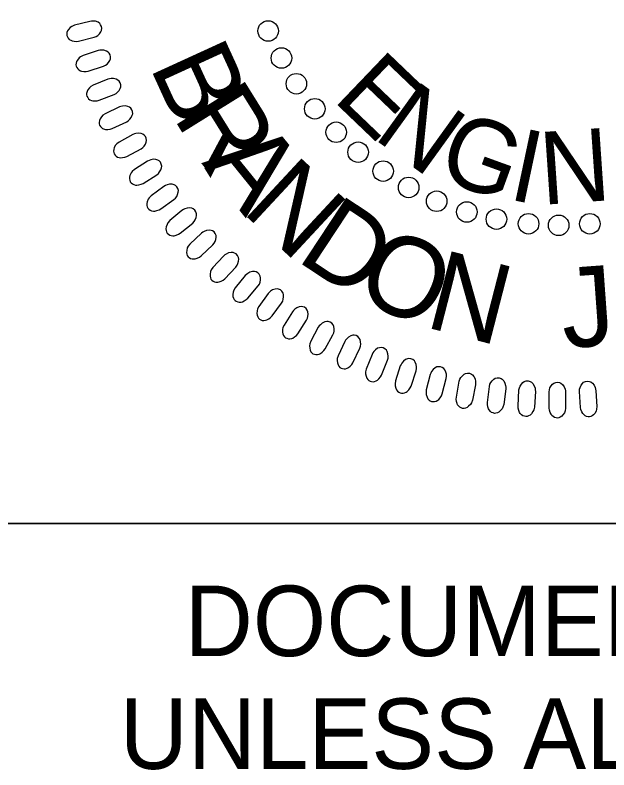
# Model space of a CAD drawing. Extents: x 502400 to 509344, y 448070 to 484209.
# Drawn here: x 507076.9 to 507123.2, y 484026.9 to 484085.8 of the extents above; entities that cross this region are included whole.
import ezdxf

# ---------------------------------------------------------------- set-up
doc = ezdxf.new("R2010")
doc.units = 0
for name, color, linetype in [('Sheet PE Seal Cell', 7, 'Continuous'), ('Sheet Profile CELL', 7, 'Continuous'), ('Sheet Sticker Exception Certification CELL', 7, 'Continuous')]:
    doc.layers.add(name, color=color, linetype=linetype)

msp = doc.modelspace()

# ---------------------------------------------------------------- linework, layer by layer
at = {"layer": 'Sheet PE Seal Cell'}
for points in [[(507082.689, 484085.332), (507081.501, 484085.028), (507081.298, 484084.937), (507081.175, 484084.852), (507081.039, 484084.701), (507080.957, 484084.58), (507080.907, 484084.451), (507080.895, 484084.34), (507080.903, 484084.226), (507080.95, 484084.123), (507081.009, 484084.015), (507081.093, 484083.928), (507081.216, 484083.851), (507081.308, 484083.813), (507081.469, 484083.785), (507081.658, 484083.772), (507081.818, 484083.79), (507083.037, 484084.094), (507083.196, 484084.158), (507083.32, 484084.237), (507083.452, 484084.363), (507083.56, 484084.506), (507083.613, 484084.62), (507083.632, 484084.787), (507083.614, 484084.937), (507083.538, 484085.072), (507083.464, 484085.161), (507083.336, 484085.26), (507083.142, 484085.333), (507082.951, 484085.354), (507082.818, 484085.35)], [(507083.343, 484083.049), (507082.176, 484082.67), (507081.979, 484082.567), (507081.862, 484082.475), (507081.735, 484082.315), (507081.661, 484082.188), (507081.62, 484082.057), (507081.615, 484081.946), (507081.63, 484081.833), (507081.684, 484081.733), (507081.749, 484081.628), (507081.838, 484081.547), (507081.966, 484081.478), (507082.059, 484081.445), (507082.223, 484081.428), (507082.412, 484081.427), (507082.571, 484081.454), (507083.768, 484081.835), (507083.922, 484081.909), (507084.042, 484081.995), (507084.165, 484082.129), (507084.263, 484082.279), (507084.31, 484082.396), (507084.318, 484082.564), (507084.291, 484082.712), (507084.207, 484082.842), (507084.127, 484082.926), (507083.993, 484083.016), (507083.795, 484083.077), (507083.603, 484083.086), (507083.471, 484083.074)], [(507084.102, 484080.811), (507082.961, 484080.361), (507082.77, 484080.245), (507082.659, 484080.145), (507082.543, 484079.978), (507082.477, 484079.847), (507082.444, 484079.714), (507082.446, 484079.602), (507082.468, 484079.49), (507082.528, 484079.394), (507082.6, 484079.293), (507082.693, 484079.218), (507082.825, 484079.158), (507082.921, 484079.131), (507083.086, 484079.124), (507083.274, 484079.134), (507083.431, 484079.172), (507084.602, 484079.627), (507084.752, 484079.71), (507084.865, 484079.803), (507084.98, 484079.945), (507085.069, 484080.101), (507085.108, 484080.221), (507085.105, 484080.389), (507085.069, 484080.535), (507084.977, 484080.659), (507084.892, 484080.738), (507084.753, 484080.82), (507084.551, 484080.868), (507084.359, 484080.865), (507084.228, 484080.845)], [(507085.001, 484078.652), (507083.891, 484078.13), (507083.709, 484078.003), (507083.604, 484077.896), (507083.499, 484077.722), (507083.441, 484077.588), (507083.416, 484077.452), (507083.425, 484077.341), (507083.454, 484077.231), (507083.52, 484077.138), (507083.598, 484077.042), (507083.697, 484076.973), (507083.832, 484076.921), (507083.929, 484076.9), (507084.093, 484076.903), (507084.281, 484076.926), (507084.435, 484076.973), (507085.576, 484077.501), (507085.719, 484077.594), (507085.827, 484077.693), (507085.932, 484077.842), (507086.012, 484078.003), (507086.043, 484078.126), (507086.03, 484078.293), (507085.984, 484078.437), (507085.884, 484078.555), (507085.794, 484078.629), (507085.651, 484078.702), (507085.446, 484078.737), (507085.255, 484078.722), (507085.125, 484078.694)], [(507086.049, 484076.503), (507084.973, 484075.913), (507084.799, 484075.775), (507084.702, 484075.661), (507084.607, 484075.482), (507084.558, 484075.343), (507084.542, 484075.207), (507084.557, 484075.096), (507084.594, 484074.988), (507084.666, 484074.9), (507084.75, 484074.809), (507084.852, 484074.746), (507084.99, 484074.702), (507085.089, 484074.688), (507085.252, 484074.701), (507085.438, 484074.736), (507085.589, 484074.792), (507086.694, 484075.391), (507086.832, 484075.493), (507086.932, 484075.599), (507087.029, 484075.754), (507087.097, 484075.919), (507087.121, 484076.043), (507087.097, 484076.21), (507087.043, 484076.351), (507086.936, 484076.462), (507086.842, 484076.53), (507086.693, 484076.593), (507086.487, 484076.616), (507086.297, 484076.589), (507086.169, 484076.553)], [(507087.205, 484074.429), (507086.169, 484073.771), (507086.003, 484073.623), (507085.914, 484073.504), (507085.83, 484073.318), (507085.79, 484073.178), (507085.783, 484073.04), (507085.805, 484072.93), (507085.848, 484072.825), (507085.926, 484072.741), (507086.015, 484072.656), (507086.121, 484072.599), (507086.261, 484072.565), (507086.36, 484072.557), (507086.523, 484072.58), (507086.707, 484072.626), (507086.853, 484072.692), (507087.919, 484073.359), (507088.05, 484073.468), (507088.144, 484073.582), (507088.23, 484073.742), (507088.288, 484073.912), (507088.304, 484074.037), (507088.27, 484074.202), (507088.207, 484074.338), (507088.093, 484074.443), (507087.995, 484074.505), (507087.842, 484074.559), (507087.635, 484074.569), (507087.447, 484074.53), (507087.322, 484074.485)], [(507088.482, 484072.454), (507087.488, 484071.733), (507087.333, 484071.574), (507087.25, 484071.45), (507087.179, 484071.259), (507087.148, 484071.116), (507087.149, 484070.978), (507087.178, 484070.871), (507087.228, 484070.767), (507087.31, 484070.689), (507087.405, 484070.61), (507087.515, 484070.56), (507087.657, 484070.534), (507087.756, 484070.533), (507087.917, 484070.566), (507088.097, 484070.623), (507088.24, 484070.698), (507089.261, 484071.431), (507089.385, 484071.549), (507089.471, 484071.667), (507089.548, 484071.833), (507089.595, 484072.006), (507089.603, 484072.131), (507089.559, 484072.294), (507089.487, 484072.427), (507089.367, 484072.524), (507089.265, 484072.579), (507089.11, 484072.624), (507088.903, 484072.621), (507088.717, 484072.57), (507088.595, 484072.518)], [(507089.885, 484070.572), (507088.939, 484069.79), (507088.794, 484069.622), (507088.72, 484069.493), (507088.661, 484069.298), (507088.638, 484069.154), (507088.648, 484069.017), (507088.684, 484068.911), (507088.74, 484068.811), (507088.827, 484068.738), (507088.926, 484068.665), (507089.039, 484068.622), (507089.182, 484068.605), (507089.282, 484068.61), (507089.44, 484068.653), (507089.616, 484068.722), (507089.754, 484068.805), (507090.727, 484069.601), (507090.844, 484069.726), (507090.922, 484069.85), (507090.988, 484070.02), (507091.025, 484070.196), (507091.024, 484070.321), (507090.97, 484070.481), (507090.89, 484070.608), (507090.764, 484070.698), (507090.659, 484070.747), (507090.501, 484070.782), (507090.295, 484070.766), (507090.113, 484070.703), (507089.994, 484070.643)], [(507091.395, 484068.802), (507090.5, 484067.962), (507090.366, 484067.785), (507090.3, 484067.652), (507090.253, 484067.453), (507090.24, 484067.308), (507090.258, 484067.171), (507090.301, 484067.067), (507090.363, 484066.972), (507090.454, 484066.904), (507090.558, 484066.837), (507090.673, 484066.802), (507090.818, 484066.794), (507090.916, 484066.805), (507091.072, 484066.858), (507091.244, 484066.937), (507091.375, 484067.03), (507092.296, 484067.885), (507092.405, 484068.017), (507092.476, 484068.146), (507092.531, 484068.32), (507092.556, 484068.497), (507092.548, 484068.622), (507092.484, 484068.778), (507092.396, 484068.901), (507092.265, 484068.982), (507092.157, 484069.024), (507091.997, 484069.049), (507091.792, 484069.02), (507091.614, 484068.946), (507091.5, 484068.879)], [(507093.131, 484067.024), (507092.29, 484066.129), (507092.167, 484065.944), (507092.11, 484065.807), (507092.075, 484065.606), (507092.071, 484065.459), (507092.098, 484065.325), (507092.147, 484065.224), (507092.215, 484065.133), (507092.31, 484065.071), (507092.419, 484065.011), (507092.535, 484064.982), (507092.68, 484064.984), (507092.778, 484065), (507092.93, 484065.063), (507093.096, 484065.153), (507093.222, 484065.254), (507094.088, 484066.165), (507094.187, 484066.304), (507094.25, 484066.437), (507094.294, 484066.614), (507094.308, 484066.792), (507094.292, 484066.917), (507094.219, 484067.068), (507094.123, 484067.186), (507093.987, 484067.258), (507093.876, 484067.293), (507093.716, 484067.309), (507093.513, 484067.266), (507093.34, 484067.182), (507093.23, 484067.108)], [(507094.821, 484065.493), (507094.038, 484064.548), (507093.927, 484064.355), (507093.878, 484064.215), (507093.856, 484064.013), (507093.862, 484063.866), (507093.897, 484063.733), (507093.952, 484063.635), (507094.026, 484063.548), (507094.124, 484063.493), (507094.236, 484063.44), (507094.354, 484063.419), (507094.499, 484063.429), (507094.596, 484063.452), (507094.743, 484063.524), (507094.903, 484063.624), (507095.023, 484063.733), (507095.83, 484064.696), (507095.921, 484064.841), (507095.974, 484064.978), (507096.008, 484065.157), (507096.011, 484065.336), (507095.986, 484065.461), (507095.903, 484065.606), (507095.801, 484065.717), (507095.661, 484065.781), (507095.547, 484065.81), (507095.386, 484065.814), (507095.187, 484065.76), (507095.019, 484065.664), (507094.914, 484065.583)], [(507096.601, 484064.093), (507095.88, 484063.1), (507095.781, 484062.901), (507095.741, 484062.757), (507095.732, 484062.554), (507095.747, 484062.408), (507095.79, 484062.278), (507095.851, 484062.184), (507095.93, 484062.102), (507096.033, 484062.052), (507096.148, 484062.006), (507096.267, 484061.992), (507096.41, 484062.012), (507096.506, 484062.041), (507096.648, 484062.123), (507096.802, 484062.233), (507096.914, 484062.348), (507097.659, 484063.36), (507097.74, 484063.511), (507097.786, 484063.651), (507097.808, 484063.832), (507097.8, 484064.011), (507097.767, 484064.132), (507097.676, 484064.274), (507097.566, 484064.378), (507097.422, 484064.433), (507097.308, 484064.454), (507097.147, 484064.449), (507096.95, 484064.381), (507096.79, 484064.276), (507096.69, 484064.188)], [(507098.503, 484062.68), (507097.846, 484061.644), (507097.759, 484061.439), (507097.728, 484061.293), (507097.732, 484061.089), (507097.756, 484060.945), (507097.808, 484060.818), (507097.874, 484060.727), (507097.959, 484060.651), (507098.063, 484060.607), (507098.181, 484060.568), (507098.301, 484060.563), (507098.443, 484060.591), (507098.536, 484060.627), (507098.673, 484060.716), (507098.82, 484060.836), (507098.924, 484060.959), (507099.604, 484062.015), (507099.676, 484062.171), (507099.713, 484062.312), (507099.723, 484062.495), (507099.703, 484062.673), (507099.663, 484062.793), (507099.564, 484062.928), (507099.448, 484063.024), (507099.3, 484063.071), (507099.185, 484063.085), (507099.025, 484063.069), (507098.833, 484062.99), (507098.679, 484062.874), (507098.585, 484062.781)], [(507100.521, 484061.464), (507099.93, 484060.389), (507099.857, 484060.179), (507099.835, 484060.032), (507099.852, 484059.829), (507099.884, 484059.686), (507099.944, 484059.562), (507100.016, 484059.476), (507100.105, 484059.405), (507100.212, 484059.369), (507100.332, 484059.337), (507100.452, 484059.338), (507100.592, 484059.376), (507100.683, 484059.417), (507100.814, 484059.516), (507100.953, 484059.644), (507101.05, 484059.773), (507101.662, 484060.871), (507101.723, 484061.03), (507101.751, 484061.174), (507101.75, 484061.357), (507101.72, 484061.533), (507101.673, 484061.65), (507101.564, 484061.778), (507101.442, 484061.867), (507101.292, 484061.905), (507101.176, 484061.912), (507101.017, 484061.886), (507100.831, 484061.794), (507100.685, 484061.67), (507100.596, 484061.571)], [(507102.58, 484060.358), (507102.058, 484059.248), (507101.998, 484059.034), (507101.986, 484058.885), (507102.015, 484058.683), (507102.056, 484058.543), (507102.124, 484058.423), (507102.201, 484058.342), (507102.295, 484058.277), (507102.404, 484058.247), (507102.525, 484058.223), (507102.645, 484058.232), (507102.783, 484058.278), (507102.871, 484058.325), (507102.995, 484058.431), (507103.126, 484058.568), (507103.215, 484058.703), (507103.757, 484059.837), (507103.808, 484060), (507103.827, 484060.145), (507103.814, 484060.328), (507103.773, 484060.502), (507103.718, 484060.616), (507103.602, 484060.736), (507103.474, 484060.818), (507103.323, 484060.846), (507103.206, 484060.845), (507103.049, 484060.81), (507102.869, 484060.707), (507102.732, 484060.573), (507102.65, 484060.469)], [(507104.708, 484059.35), (507104.256, 484058.209), (507104.21, 484057.991), (507104.207, 484057.842), (507104.249, 484057.643), (507104.298, 484057.505), (507104.374, 484057.39), (507104.456, 484057.314), (507104.553, 484057.254), (507104.664, 484057.232), (507104.787, 484057.215), (507104.906, 484057.232), (507105.04, 484057.287), (507105.125, 484057.339), (507105.243, 484057.453), (507105.364, 484057.598), (507105.444, 484057.738), (507105.914, 484058.903), (507105.956, 484059.069), (507105.965, 484059.215), (507105.941, 484059.397), (507105.888, 484059.568), (507105.827, 484059.678), (507105.703, 484059.792), (507105.571, 484059.865), (507105.418, 484059.883), (507105.302, 484059.875), (507105.147, 484059.829), (507104.974, 484059.716), (507104.845, 484059.573), (507104.77, 484059.464)], [(507106.917, 484058.447), (507106.537, 484057.281), (507106.505, 484057.06), (507106.511, 484056.911), (507106.565, 484056.715), (507106.624, 484056.581), (507106.706, 484056.47), (507106.793, 484056.401), (507106.894, 484056.347), (507107.006, 484056.331), (507107.13, 484056.322), (507107.247, 484056.346), (507107.378, 484056.41), (507107.459, 484056.467), (507107.57, 484056.588), (507107.682, 484056.741), (507107.753, 484056.885), (507108.149, 484058.078), (507108.18, 484058.246), (507108.18, 484058.393), (507108.144, 484058.572), (507108.081, 484058.739), (507108.013, 484058.846), (507107.882, 484058.951), (507107.746, 484059.016), (507107.592, 484059.025), (507107.477, 484059.009), (507107.325, 484058.954), (507107.159, 484058.83), (507107.039, 484058.679), (507106.971, 484058.566)], [(507109.25, 484057.774), (507108.944, 484056.586), (507108.926, 484056.365), (507108.941, 484056.216), (507109.008, 484056.024), (507109.074, 484055.893), (507109.164, 484055.789), (507109.255, 484055.723), (507109.358, 484055.676), (507109.472, 484055.668), (507109.595, 484055.668), (507109.711, 484055.699), (507109.837, 484055.77), (507109.915, 484055.831), (507110.018, 484055.96), (507110.12, 484056.119), (507110.182, 484056.268), (507110.502, 484057.483), (507110.522, 484057.653), (507110.513, 484057.799), (507110.466, 484057.976), (507110.393, 484058.139), (507110.318, 484058.241), (507110.181, 484058.338), (507110.042, 484058.394), (507109.886, 484058.393), (507109.773, 484058.37), (507109.625, 484058.306), (507109.467, 484058.171), (507109.357, 484058.014), (507109.296, 484057.896)], [(507112.772, 484056.987), (507112.541, 484055.781), (507112.463, 484055.573), (507112.386, 484055.446), (507112.244, 484055.3), (507112.128, 484055.211), (507112.003, 484055.154), (507111.892, 484055.134), (507111.778, 484055.136), (507111.673, 484055.176), (507111.56, 484055.228), (507111.469, 484055.306), (507111.385, 484055.424), (507111.341, 484055.513), (507111.303, 484055.673), (507111.278, 484055.861), (507111.286, 484056.022), (507111.514, 484057.257), (507111.568, 484057.42), (507111.639, 484057.548), (507111.757, 484057.688), (507111.893, 484057.804), (507112.003, 484057.865), (507112.168, 484057.894), (507112.32, 484057.885), (507112.458, 484057.818), (507112.552, 484057.749), (507112.658, 484057.628), (507112.743, 484057.439), (507112.776, 484057.249), (507112.781, 484057.117)], [(507115.138, 484056.661), (507114.983, 484055.443), (507114.919, 484055.231), (507114.849, 484055.098), (507114.717, 484054.944), (507114.607, 484054.848), (507114.485, 484054.782), (507114.377, 484054.756), (507114.263, 484054.751), (507114.155, 484054.785), (507114.039, 484054.829), (507113.943, 484054.901), (507113.852, 484055.014), (507113.802, 484055.101), (507113.754, 484055.258), (507113.718, 484055.443), (507113.715, 484055.604), (507113.866, 484056.851), (507113.909, 484057.017), (507113.972, 484057.15), (507114.08, 484057.297), (507114.209, 484057.421), (507114.316, 484057.488), (507114.479, 484057.528), (507114.63, 484057.529), (507114.773, 484057.47), (507114.871, 484057.408), (507114.985, 484057.293), (507115.081, 484057.11), (507115.126, 484056.923), (507115.139, 484056.791)], [(507117.455, 484056.463), (507117.377, 484055.239), (507117.326, 484055.022), (507117.265, 484054.886), (507117.143, 484054.724), (507117.039, 484054.62), (507116.922, 484054.548), (507116.815, 484054.514), (507116.701, 484054.502), (507116.591, 484054.529), (507116.474, 484054.566), (507116.373, 484054.632), (507116.275, 484054.739), (507116.22, 484054.822), (507116.162, 484054.976), (507116.114, 484055.159), (507116.102, 484055.32), (507116.173, 484056.574), (507116.207, 484056.741), (507116.261, 484056.878), (507116.36, 484057.032), (507116.48, 484057.164), (507116.583, 484057.238), (507116.743, 484057.287), (507116.894, 484057.298), (507117.041, 484057.248), (507117.141, 484057.192), (507117.262, 484057.085), (507117.37, 484056.908), (507117.427, 484056.724), (507117.448, 484056.594)], [(507119.808, 484056.391), (507119.808, 484055.164), (507119.77, 484054.946), (507119.718, 484054.805), (507119.606, 484054.636), (507119.508, 484054.526), (507119.396, 484054.446), (507119.292, 484054.407), (507119.18, 484054.387), (507119.068, 484054.407), (507118.948, 484054.437), (507118.843, 484054.496), (507118.738, 484054.597), (507118.679, 484054.676), (507118.611, 484054.826), (507118.552, 484055.005), (507118.529, 484055.165), (507118.522, 484056.421), (507118.545, 484056.591), (507118.59, 484056.73), (507118.679, 484056.89), (507118.791, 484057.03), (507118.889, 484057.11), (507119.046, 484057.169), (507119.196, 484057.189), (507119.345, 484057.149), (507119.45, 484057.099), (507119.577, 484057), (507119.696, 484056.83), (507119.764, 484056.65), (507119.793, 484056.521)], [(507122.175, 484056.514), (507122.251, 484055.289), (507122.228, 484055.068), (507122.185, 484054.925), (507122.083, 484054.749), (507121.994, 484054.633), (507121.886, 484054.547), (507121.785, 484054.501), (507121.674, 484054.474), (507121.561, 484054.487), (507121.44, 484054.509), (507121.331, 484054.562), (507121.22, 484054.656), (507121.156, 484054.731), (507121.08, 484054.876), (507121.009, 484055.052), (507120.976, 484055.21), (507120.89, 484056.463), (507120.902, 484056.634), (507120.938, 484056.776), (507121.018, 484056.941), (507121.121, 484057.087), (507121.213, 484057.173), (507121.366, 484057.243), (507121.514, 484057.272), (507121.665, 484057.241), (507121.773, 484057.198), (507121.906, 484057.107), (507122.036, 484056.944), (507122.115, 484056.769), (507122.153, 484056.642)]]:
    msp.add_lwpolyline(points, close=True, dxfattribs=at)
for centre in [(507096.606, 484084.58), (507097.641, 484082.469), (507098.81, 484080.465), (507100.242, 484078.512), (507101.914, 484076.679), (507103.625, 484075.125), (507105.576, 484073.65), (507107.566, 484072.375), (507109.755, 484071.299), (507112.104, 484070.461), (507114.413, 484069.903), (507116.921, 484069.544), (507121.699, 484069.542), (507119.27, 484069.423)]:
    msp.add_circle(centre, 0.801, dxfattribs=at)
at = {"layer": 'Sheet Profile CELL'}
msp.add_lwpolyline([(507069.03, 484158.662), (507169.08, 484158.662), (507169.08, 484046.162), (507069.03, 484046.162)], close=True, dxfattribs=at)
at = {"layer": 'Sheet Sticker Exception Certification CELL'}
msp.add_line((507069.03, 484046.162), (507269.067, 484046.162), dxfattribs=at)
msp.add_line((507069.03, 484046.162), (507269.067, 484046.162), dxfattribs=at)

# ---------------------------------------------------------------- texts
at = {"layer": 'Sheet PE Seal Cell'}
for s, height, rotation, p in [('B', 6.236, 294.5897, (507087.323, 484081.852)), ('E', 5.669, 316.26559, (507101.563, 484079.23)), ('R', 6.236, 301.86473, (507089.134, 484077.895)), ('N', 5.669, 324.20538, (507104.698, 484076.275)), ('G', 5.669, 340.08498, (507109.592, 484073.177)), ('I', 5.669, 348.02477, (507115.221, 484071.487)), ('N', 5.669, 3.90437, (507117.974, 484071.015)), ('A', 6.236, 308.98157, (507091.377, 484074.277)), ('N', 6.236, 317.09274, (507094.456, 484070.529)), ('D', 6.236, 326.58243, (507098.686, 484066.748)), ('O', 6.236, 335.45066, (507103.152, 484063.89)), ('N', 6.236, 345.5505, (507108.704, 484061.518)), ('J', 6.236, 4.1457, (507119.655, 484059.826))]:
    msp.add_text(s, height=height, rotation=rotation, dxfattribs=at).set_placement(p)
at = {"layer": 'Sheet Sticker Exception Certification CELL'}
for s, p in [('DOCUMENT NOT CONSIDERED FINAL', (507090.101, 484035.816)), ('DOCUMENT NOT CONSIDERED FINAL', (507090.101, 484035.816)), ('UNLESS ALL SIGNATURES COMPLETED', (507085.03, 484027.016)), ('UNLESS ALL SIGNATURES COMPLETED', (507085.03, 484027.016))]:
    msp.add_text(s, height=5.5, dxfattribs=at).set_placement(p)

doc.saveas('drawing.dxf')
